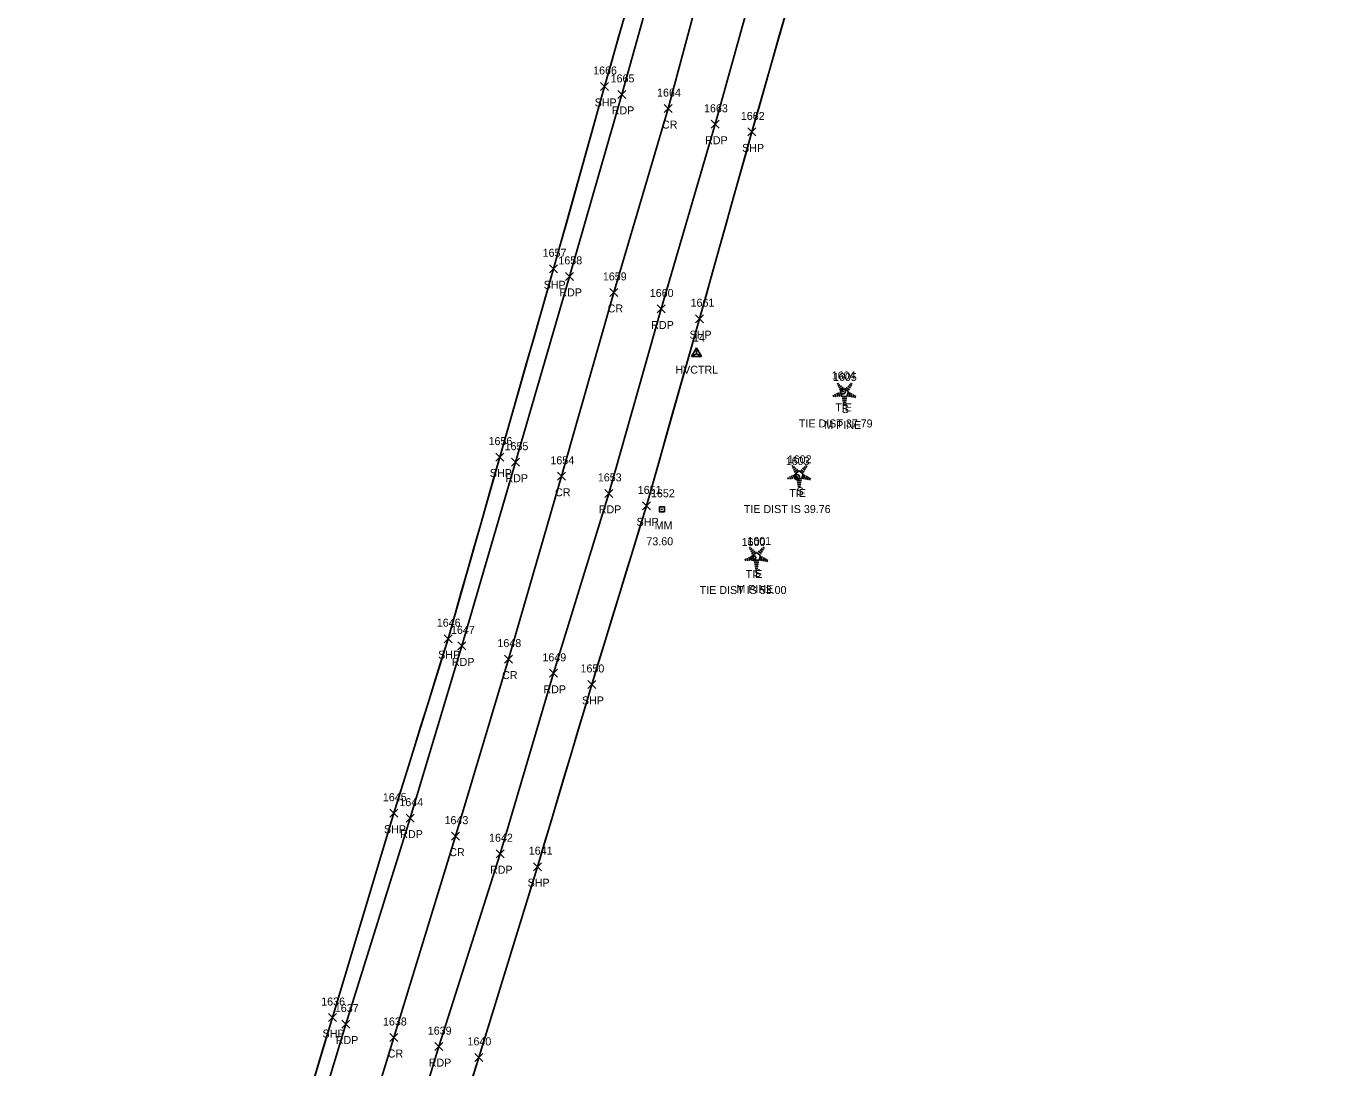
# Model space of a CAD drawing. Extents: x 1688195 to 1692013, y 424605 to 441234.
# Drawn here: x 1690035.6 to 1690361.3, y 433370.5 to 433631 of the extents above; entities that cross this region are included whole.
import ezdxf

# ---------------------------------------------------------------- set-up
doc = ezdxf.new("R2010")
doc.units = 0
for name, color, linetype in [('C_A', 7, 'Continuous'), ('C_C', 7, 'Continuous'), ('C_I', 7, 'Continuous'), ('CBP', 7, 'Continuous'), ('CPSM', 7, 'Continuous'), ('L_A', 7, 'Continuous'), ('L_C', 7, 'Continuous'), ('L_I', 7, 'Continuous'), ('LSOGP', 7, 'Continuous'), ('LTC', 7, 'Continuous'), ('P_A', 7, 'Continuous'), ('P_I', 7, 'Continuous'), ('P_TIC', 7, 'Continuous'), ('PET', 7, 'Continuous'), ('PRC', 7, 'Continuous'), ('PSP', 7, 'Continuous'), ('S_A', 7, 'Continuous'), ('S_C', 7, 'Continuous'), ('S_I', 7, 'Continuous'), ('SRM', 7, 'Continuous')]:
    doc.layers.add(name, color=color, linetype=linetype)

msp = doc.modelspace()

# ---------------------------------------------------------------- linework, layer by layer
at = {"layer": 'CBP'}
for centre, radius in [((1690239.85, 433539.6), 0.625), ((1690239.85, 433539.6), 0.0833), ((1690228.36, 433518.2), 0.625), ((1690228.36, 433518.2), 0.0833), ((1690217.44, 433497.96), 0.625), ((1690217.44, 433497.96), 0.0833)]:
    msp.add_circle(centre, radius, dxfattribs=at)
at = {"layer": 'CPSM'}
for p, q in [((1690202, 433548.31), (1690203.25, 433550.48)), ((1690202, 433548.31), (1690203.25, 433549.04)), ((1690202, 433548.31), (1690204.5, 433548.31)), ((1690204.5, 433548.31), (1690203.25, 433550.48)), ((1690203.25, 433549.04), (1690203.25, 433550.48)), ((1690203.25, 433549.04), (1690203.25, 433549.04)), ((1690203.25, 433549.04), (1690204.5, 433548.31))]:
    msp.add_line(p, q, dxfattribs=at)
at = {"layer": 'LSOGP'}
for points in [[(1690185.39, 433633.95), (1690183.67, 433627.91), (1690181.95, 433621.88), (1690180.24, 433615.85), (1690178.65, 433610.15), (1690177.05, 433604.45), (1690175.46, 433598.75), (1690173.87, 433593.05), (1690172.28, 433587.36), (1690170.69, 433581.66), (1690169.09, 433575.96), (1690167.5, 433570.26), (1690165.82, 433564.38), (1690164.13, 433558.49), (1690162.45, 433552.61), (1690160.77, 433546.72), (1690159.08, 433540.84), (1690157.4, 433534.95), (1690155.72, 433529.07), (1690154.03, 433523.19), (1690152.42, 433517.51), (1690150.8, 433511.84), (1690149.19, 433506.16), (1690147.57, 433500.49), (1690145.96, 433494.81), (1690144.34, 433489.14), (1690142.72, 433483.46), (1690141.11, 433477.79), (1690139.41, 433472.34), (1690137.72, 433466.88), (1690136.03, 433461.43), (1690134.33, 433455.98), (1690132.64, 433450.52), (1690130.95, 433445.07), (1690129.25, 433439.62), (1690127.56, 433434.16), (1690125.64, 433427.78), (1690123.72, 433421.39), (1690121.8, 433415.01), (1690119.88, 433408.62), (1690117.96, 433402.23), (1690116.04, 433395.85), (1690114.12, 433389.46), (1690112.2, 433383.07), (1690110.52, 433377.45), (1690108.84, 433371.83), (1690107.16, 433366.21)], [(1690147.02, 433367.29), (1690148.81, 433373.11), (1690150.64, 433379.07), (1690152.48, 433385.03), (1690154.31, 433390.99), (1690156.14, 433396.95), (1690157.98, 433402.91), (1690159.81, 433408.87), (1690161.64, 433414.83), (1690163.48, 433420.79), (1690165.17, 433426.48), (1690166.87, 433432.18), (1690168.57, 433437.88), (1690170.27, 433443.57), (1690171.96, 433449.27), (1690173.66, 433454.96), (1690175.36, 433460.66), (1690177.06, 433466.35), (1690178.76, 433471.93), (1690180.47, 433477.51), (1690182.18, 433483.09), (1690183.89, 433488.67), (1690185.59, 433494.25), (1690187.3, 433499.83), (1690189.01, 433505.41), (1690190.71, 433510.99), (1690192.37, 433516.84), (1690194.03, 433522.69), (1690195.68, 433528.54), (1690197.34, 433534.39), (1690199, 433540.24), (1690200.65, 433546.09), (1690202.31, 433551.94), (1690203.97, 433557.79), (1690205.61, 433563.63), (1690207.25, 433569.46), (1690208.89, 433575.3), (1690210.53, 433581.14), (1690212.17, 433586.97), (1690213.81, 433592.81), (1690215.45, 433598.65), (1690217.09, 433604.48), (1690218.78, 433610.42), (1690220.47, 433616.35), (1690222.16, 433622.28), (1690223.85, 433628.22), (1690225.54, 433634.15)]]:
    msp.add_lwpolyline(points, dxfattribs=at)
at = {"layer": 'LTC'}
for p, q in [((1690238.36, 433541.42), (1690238.71, 433541.68)), ((1690241.76, 433541.66), (1690242.18, 433541.36)), ((1690237.39, 433538.7), (1690237.54, 433538.23)), ((1690237.85, 433538.92), (1690238.06, 433538.26)), ((1690238.3, 433539.13), (1690238.57, 433538.3)), ((1690238.57, 433540.95), (1690239.1, 433541.34)), ((1690238.76, 433539.35), (1690239.09, 433538.33)), ((1690238.78, 433540.49), (1690239.48, 433541)), ((1690238.99, 433540.02), (1690239.87, 433540.66)), ((1690239.21, 433539.57), (1690240.22, 433540.3)), ((1690239.21, 433539.57), (1690239.6, 433538.37)), ((1690240.83, 433538.37), (1690239.6, 433538.37)), ((1690240.22, 433540.3), (1690241.22, 433539.58)), ((1690240.64, 433540.62), (1690241.45, 433540.03)), ((1690241.22, 433539.58), (1690240.83, 433538.37)), ((1690241.02, 433540.96), (1690241.69, 433540.47)), ((1690241.66, 433539.31), (1690241.32, 433538.27)), ((1690241.39, 433541.31), (1690241.94, 433540.91)), ((1690242.1, 433539.06), (1690241.82, 433538.17)), ((1690242.55, 433538.81), (1690242.31, 433538.08)), ((1690242.99, 433538.56), (1690242.81, 433537.98)), ((1690240.79, 433537.87), (1690239.65, 433537.87)), ((1690240.71, 433537.37), (1690239.72, 433537.37)), ((1690240.62, 433536.87), (1690239.79, 433536.87)), ((1690240.54, 433536.37), (1690239.87, 433536.37)), ((1690227.05, 433520.85), (1690227.4, 433521.1)), ((1690227.26, 433520.38), (1690227.78, 433520.76)), ((1690227.44, 433518.77), (1690227.78, 433517.75)), ((1690227.47, 433519.91), (1690228.17, 433520.43)), ((1690227.67, 433519.45), (1690228.55, 433520.09)), ((1690227.9, 433518.99), (1690228.91, 433519.73)), ((1690227.9, 433518.99), (1690228.29, 433517.8)), ((1690228.91, 433519.73), (1690229.91, 433519)), ((1690229.33, 433520.04), (1690230.14, 433519.45)), ((1690229.91, 433519), (1690229.52, 433517.8)), ((1690229.7, 433520.39), (1690230.38, 433519.9)), ((1690230.35, 433518.73), (1690230.01, 433517.69)), ((1690230.07, 433520.74), (1690230.62, 433520.34)), ((1690230.44, 433521.09), (1690230.86, 433520.78)), ((1690226.08, 433518.12), (1690226.23, 433517.66)), ((1690226.53, 433518.34), (1690226.75, 433517.69)), ((1690226.99, 433518.56), (1690227.26, 433517.72)), ((1690229.52, 433517.8), (1690228.29, 433517.8)), ((1690229.48, 433517.3), (1690228.33, 433517.3)), ((1690229.39, 433516.8), (1690228.41, 433516.8)), ((1690229.31, 433516.3), (1690228.48, 433516.3)), ((1690229.23, 433515.8), (1690228.55, 433515.8)), ((1690230.79, 433518.48), (1690230.5, 433517.6)), ((1690231.23, 433518.23), (1690231, 433517.5)), ((1690231.68, 433517.98), (1690231.49, 433517.41)), ((1690216.39, 433500.44), (1690216.74, 433500.7)), ((1690216.59, 433499.97), (1690217.12, 433500.36)), ((1690216.8, 433499.51), (1690217.51, 433500.02)), ((1690217.01, 433499.04), (1690217.89, 433499.68)), ((1690217.24, 433498.59), (1690218.25, 433499.32)), ((1690218.25, 433499.32), (1690219.25, 433498.6)), ((1690218.67, 433499.63), (1690219.48, 433499.05)), ((1690219.04, 433499.98), (1690219.72, 433499.49)), ((1690219.41, 433500.33), (1690219.96, 433499.93)), ((1690219.78, 433500.68), (1690220.2, 433500.37)), ((1690215.42, 433497.72), (1690215.57, 433497.25)), ((1690215.87, 433497.93), (1690216.08, 433497.28)), ((1690216.33, 433498.15), (1690216.6, 433497.32)), ((1690216.78, 433498.37), (1690217.11, 433497.35)), ((1690217.24, 433498.59), (1690217.63, 433497.39)), ((1690218.86, 433497.39), (1690217.63, 433497.39)), ((1690218.82, 433496.89), (1690217.67, 433496.89)), ((1690218.73, 433496.39), (1690217.75, 433496.39)), ((1690218.65, 433495.89), (1690217.82, 433495.89)), ((1690219.25, 433498.6), (1690218.86, 433497.39)), ((1690219.68, 433498.33), (1690219.35, 433497.29)), ((1690220.13, 433498.07), (1690219.84, 433497.19)), ((1690220.57, 433497.82), (1690220.34, 433497.1)), ((1690221.02, 433497.57), (1690220.83, 433497)), ((1690218.57, 433495.39), (1690217.89, 433495.39))]:
    msp.add_line(p, q, dxfattribs=at)
at = {"layer": 'P_TIC'}
for points in [[(1690179.24, 433614.85), (1690181.24, 433616.85)], [(1690181.24, 433614.85), (1690179.24, 433616.85)], [(1690183.55, 433612.87), (1690185.55, 433614.87)], [(1690185.55, 433612.87), (1690183.55, 433614.87)], [(1690195.15, 433609.32), (1690197.15, 433611.32)], [(1690197.15, 433609.32), (1690195.15, 433611.32)], [(1690206.9, 433605.4), (1690208.9, 433607.4)], [(1690208.9, 433605.4), (1690206.9, 433607.4)], [(1690216.09, 433603.48), (1690218.09, 433605.48)], [(1690218.09, 433603.48), (1690216.09, 433605.48)], [(1690166.5, 433569.26), (1690168.5, 433571.26)], [(1690168.5, 433569.26), (1690166.5, 433571.26)], [(1690170.45, 433567.37), (1690172.45, 433569.37)], [(1690172.45, 433567.37), (1690170.45, 433569.37)], [(1690181.57, 433563.36), (1690183.57, 433565.36)], [(1690183.57, 433563.36), (1690181.57, 433565.36)], [(1690193.42, 433559.22), (1690195.42, 433561.22)], [(1690195.42, 433559.22), (1690193.42, 433561.22)], [(1690202.97, 433556.79), (1690204.97, 433558.79)], [(1690204.97, 433556.79), (1690202.97, 433558.79)], [(1690153.03, 433522.19), (1690155.03, 433524.19)], [(1690155.03, 433522.19), (1690153.03, 433524.19)], [(1690156.99, 433520.91), (1690158.99, 433522.91)], [(1690158.99, 433520.91), (1690156.99, 433522.91)], [(1690168.45, 433517.39), (1690170.45, 433519.39)], [(1690170.45, 433517.39), (1690168.45, 433519.39)], [(1690180.3, 433513.12), (1690182.3, 433515.12)], [(1690182.3, 433513.12), (1690180.3, 433515.12)], [(1690189.71, 433509.99), (1690191.71, 433511.99)], [(1690191.71, 433509.99), (1690189.71, 433511.99)], [(1690140.11, 433476.79), (1690142.11, 433478.79)], [(1690142.11, 433476.79), (1690140.11, 433478.79)], [(1690143.59, 433474.99), (1690145.59, 433476.99)], [(1690145.59, 433474.99), (1690143.59, 433476.99)], [(1690155.2, 433471.69), (1690157.2, 433473.69)], [(1690157.2, 433471.69), (1690155.2, 433473.69)], [(1690166.46, 433468.13), (1690168.46, 433470.13)], [(1690168.46, 433468.13), (1690166.46, 433470.13)], [(1690176.06, 433465.35), (1690178.06, 433467.35)], [(1690178.06, 433465.35), (1690176.06, 433467.35)], [(1690126.56, 433433.16), (1690128.56, 433435.16)], [(1690128.56, 433433.16), (1690126.56, 433435.16)], [(1690130.69, 433431.92), (1690132.69, 433433.92)], [(1690132.69, 433431.92), (1690130.69, 433433.92)], [(1690141.98, 433427.42), (1690143.98, 433429.42)], [(1690143.98, 433427.42), (1690141.98, 433429.42)], [(1690153.11, 433423.03), (1690155.11, 433425.03)], [(1690155.11, 433423.03), (1690153.11, 433425.03)], [(1690162.48, 433419.79), (1690164.48, 433421.79)], [(1690164.48, 433419.79), (1690162.48, 433421.79)], [(1690111.2, 433382.07), (1690113.2, 433384.07)], [(1690113.2, 433382.07), (1690111.2, 433384.07)], [(1690114.56, 433380.44), (1690116.56, 433382.44)], [(1690116.56, 433380.44), (1690114.56, 433382.44)], [(1690126.59, 433377.08), (1690128.59, 433379.08)], [(1690128.59, 433377.08), (1690126.59, 433379.08)], [(1690137.8, 433374.8), (1690139.8, 433376.8)], [(1690139.8, 433374.8), (1690137.8, 433376.8)], [(1690147.81, 433372.11), (1690149.81, 433374.11)], [(1690149.81, 433372.11), (1690147.81, 433374.11)]]:
    msp.add_lwpolyline(points, dxfattribs=at)
at = {"layer": 'PET'}
for points in [[(1690039.31, 433141.76), (1690054.57, 433188.01), (1690071.92, 433240.08), (1690086.85, 433287.62), (1690102.26, 433337.25), (1690115.56, 433381.44), (1690131.69, 433432.92), (1690144.59, 433475.99), (1690157.99, 433521.91), (1690171.45, 433568.37), (1690184.55, 433613.87), (1690198.24, 433662.87), (1690210.27, 433706.27), (1690223.3, 433755.05), (1690235.73, 433802.19), (1690247.98, 433848.83), (1690259.12, 433893.75), (1690270.77, 433940.97), (1690282.64, 433988.24), (1690294.48, 434036.45), (1690304.88, 434079.93), (1690315.83, 434126.81), (1690327.01, 434174.5)], [(1690062.43, 433135.09), (1690077.18, 433180.86), (1690093.3, 433230.54), (1690108.95, 433280.36), (1690124.55, 433328.94), (1690138.8, 433375.8), (1690154.11, 433424.03), (1690167.46, 433469.13), (1690181.3, 433514.12), (1690194.42, 433560.22), (1690207.9, 433606.4), (1690221.31, 433654.72), (1690234.27, 433699.14), (1690246.95, 433747.13), (1690259.85, 433795.38), (1690271.49, 433841.23), (1690283.29, 433886.64), (1690294.95, 433934.74), (1690306.71, 433982.08), (1690318.31, 434029.92), (1690329.53, 434076.11), (1690339.32, 434119.7), (1690350.76, 434169.07)]]:
    msp.add_lwpolyline(points, dxfattribs=at)
at = {"layer": 'PRC'}
msp.add_lwpolyline([(1690050.72, 433137.42), (1690066, 433183.94), (1690082.54, 433234.94), (1690098.12, 433283.75), (1690113.76, 433332.8), (1690127.59, 433378.08), (1690142.98, 433428.42), (1690156.2, 433472.69), (1690169.45, 433518.39), (1690182.57, 433564.36), (1690196.15, 433610.32), (1690209.04, 433658.61), (1690222.03, 433703.01), (1690235.13, 433751.31), (1690247.61, 433798.68), (1690259.48, 433845.32), (1690270.53, 433890.06), (1690282.69, 433938.03), (1690294.79, 433985.05), (1690306.25, 434033.34), (1690316.78, 434076.73), (1690327.68, 434123), (1690339.72, 434172)], dxfattribs=at)
at = {"layer": 'PSP'}
for points in [[(1690035.62, 433142.9), (1690050.91, 433189.18), (1690068.06, 433241.76), (1690083.28, 433289.68), (1690098.76, 433338.11), (1690112.2, 433383.07), (1690127.56, 433434.16), (1690141.11, 433477.79), (1690154.03, 433523.19), (1690167.5, 433570.26), (1690180.24, 433615.85), (1690193.97, 433664.12), (1690206.14, 433708.77), (1690219.24, 433756.09), (1690231.62, 433803.9), (1690243.68, 433849.77), (1690255.36, 433895.72), (1690266.7, 433941.79), (1690278.49, 433989.33), (1690289.98, 434036.92), (1690300.41, 434080.72), (1690311.54, 434127.65), (1690322.57, 434175.56)], [(1690072.07, 433131.46), (1690087.47, 433177.91), (1690103.11, 433227.19), (1690119.42, 433278.09), (1690134.51, 433326.59), (1690148.81, 433373.11), (1690163.48, 433420.79), (1690177.06, 433466.35), (1690190.71, 433510.99), (1690203.97, 433557.79), (1690217.09, 433604.48), (1690230.61, 433651.95), (1690243.15, 433696.65), (1690256.23, 433744.76), (1690269.19, 433792.83), (1690281.36, 433839.28), (1690292.85, 433884.41), (1690304.72, 433932.16), (1690316.05, 433979.62), (1690327.5, 434027.37), (1690338.5, 434072.71), (1690349.06, 434117.45), (1690361.33, 434170.48)]]:
    msp.add_lwpolyline(points, dxfattribs=at)
at = {"layer": 'SRM'}
msp.add_lwpolyline([(1690193.96, 433510.76), (1690195.21, 433510.76), (1690195.21, 433509.51), (1690193.96, 433509.51)], close=True, dxfattribs=at)
msp.add_circle((1690194.58, 433510.14), 0.0833, dxfattribs=at)

# ---------------------------------------------------------------- texts
at = {"layer": 'C_A'}
for s, p in [('HVCTRL', (1690197.95, 433544.04)), ('TIE', (1690237.93, 433534.6)), ('TIE', (1690226.43, 433513.2)), ('TIE', (1690215.52, 433492.96))]:
    msp.add_text(s, height=2, dxfattribs=at).set_placement(p)
at = {"layer": 'C_C'}
for s, p in [('TIE DIST 37.79', (1690228.82, 433530.6)), ('TIE DIST IS 39.76', (1690215.06, 433509.2)), ('TIE DIST IS 53.00', (1690204.03, 433488.96))]:
    msp.add_text(s, height=2, dxfattribs=at).set_placement(p)
at = {"layer": 'C_I'}
for s, p in [('14', (1690202.36, 433552.04)), ('1604', (1690237.04, 433542.6)), ('1603', (1690225.54, 433521.2)), ('1600', (1690214.53, 433500.96))]:
    msp.add_text(s, height=2, dxfattribs=at).set_placement(p)
at = {"layer": 'L_A'}
for p in [(1690239.55, 433534.21), (1690228.24, 433513.64), (1690217.58, 433493.23)]:
    msp.add_text('S', height=2, dxfattribs=at).set_placement(p)
at = {"layer": 'L_C'}
for p in [(1690235.19, 433530.21), (1690213.21, 433489.23)]:
    msp.add_text('M PINE', height=2, dxfattribs=at).set_placement(p)
at = {"layer": 'L_I'}
for s, p in [('1605', (1690237.34, 433542.21)), ('1602', (1690226.03, 433521.64)), ('1601', (1690215.94, 433501.23))]:
    msp.add_text(s, height=2, dxfattribs=at).set_placement(p)
at = {"layer": 'LTC'}
for p in [(1690240.11, 433539.32), (1690228.79, 433518.74), (1690218.13, 433498.33)]:
    msp.add_text('.', height=1.04, rotation=270, dxfattribs=at).set_placement(p)
at = {"layer": 'P_A'}
for s, p in [('SHP', (1690177.77, 433610.85)), ('RDP', (1690182.03, 433608.87)), ('CR', (1690194.59, 433605.32)), ('RDP', (1690205.38, 433601.4)), ('SHP', (1690214.63, 433599.48)), ('SHP', (1690165.04, 433565.26)), ('RDP', (1690168.94, 433563.37)), ('CR', (1690181.01, 433559.36)), ('RDP', (1690191.91, 433555.22)), ('SHP', (1690201.5, 433552.79)), ('SHP', (1690151.57, 433518.19)), ('RDP', (1690155.47, 433516.91)), ('CR', (1690167.88, 433513.39)), ('RDP', (1690178.79, 433509.12)), ('SHP', (1690188.25, 433505.99)), ('SHP', (1690138.64, 433472.79)), ('RDP', (1690142.08, 433470.99)), ('CR', (1690154.63, 433467.69)), ('RDP', (1690164.95, 433464.13)), ('SHP', (1690174.59, 433461.35)), ('SHP', (1690125.1, 433429.16)), ('RDP', (1690129.17, 433427.92)), ('CR', (1690141.42, 433423.42)), ('RDP', (1690151.6, 433419.03)), ('SHP', (1690161.01, 433415.79)), ('SHP', (1690109.74, 433378.07)), ('RDP', (1690113.05, 433376.44)), ('CR', (1690126.02, 433373.08)), ('RDP', (1690136.29, 433370.8))]:
    msp.add_text(s, height=2, dxfattribs=at).set_placement(p)
at = {"layer": 'P_I'}
for s, p in [('1666', (1690177.39, 433618.85)), ('1665', (1690181.76, 433616.87)), ('1664', (1690193.37, 433613.32)), ('1663', (1690205.11, 433609.4)), ('1662', (1690214.31, 433607.48)), ('1657', (1690164.76, 433573.26)), ('1658', (1690168.71, 433571.37)), ('1659', (1690179.82, 433567.36)), ('1660', (1690191.55, 433563.22)), ('1661', (1690201.75, 433560.79)), ('1656', (1690151.24, 433526.19)), ('1655', (1690155.25, 433524.91)), ('1654', (1690166.71, 433521.39)), ('1653', (1690178.56, 433517.12)), ('1651', (1690188.54, 433513.99)), ('1646', (1690138.31, 433480.79)), ('1647', (1690141.85, 433478.99)), ('1648', (1690153.46, 433475.69)), ('1649', (1690164.71, 433472.13)), ('1650', (1690174.23, 433469.35)), ('1645', (1690124.82, 433437.16)), ('1644', (1690128.95, 433435.92)), ('1643', (1690140.24, 433431.42)), ('1642', (1690151.37, 433427.03)), ('1641', (1690161.3, 433423.79)), ('1636', (1690109.41, 433386.07)), ('1637', (1690112.82, 433384.44)), ('1638', (1690124.85, 433381.08)), ('1639', (1690136.05, 433378.8)), ('1640', (1690145.98, 433376.11))]:
    msp.add_text(s, height=2, dxfattribs=at).set_placement(p)
at = {"layer": 'S_A'}
msp.add_text('MM', height=2, dxfattribs=at).set_placement((1690192.77, 433505.14))
at = {"layer": 'S_C'}
msp.add_text('73.60', height=2, dxfattribs=at).set_placement((1690190.7, 433501.14))
at = {"layer": 'S_I'}
msp.add_text('1652', height=2, dxfattribs=at).set_placement((1690191.84, 433513.14))

doc.saveas('drawing.dxf')
